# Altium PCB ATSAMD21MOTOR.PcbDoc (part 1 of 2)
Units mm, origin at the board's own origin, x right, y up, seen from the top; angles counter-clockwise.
Board outline 45.2 x 50.2 mm, 4 copper layers (Top Layer, GND, POWER, Bottom Layer), stack 0.8 mm thick; 92 components, 102 nets, 421 pads, 273 vias.
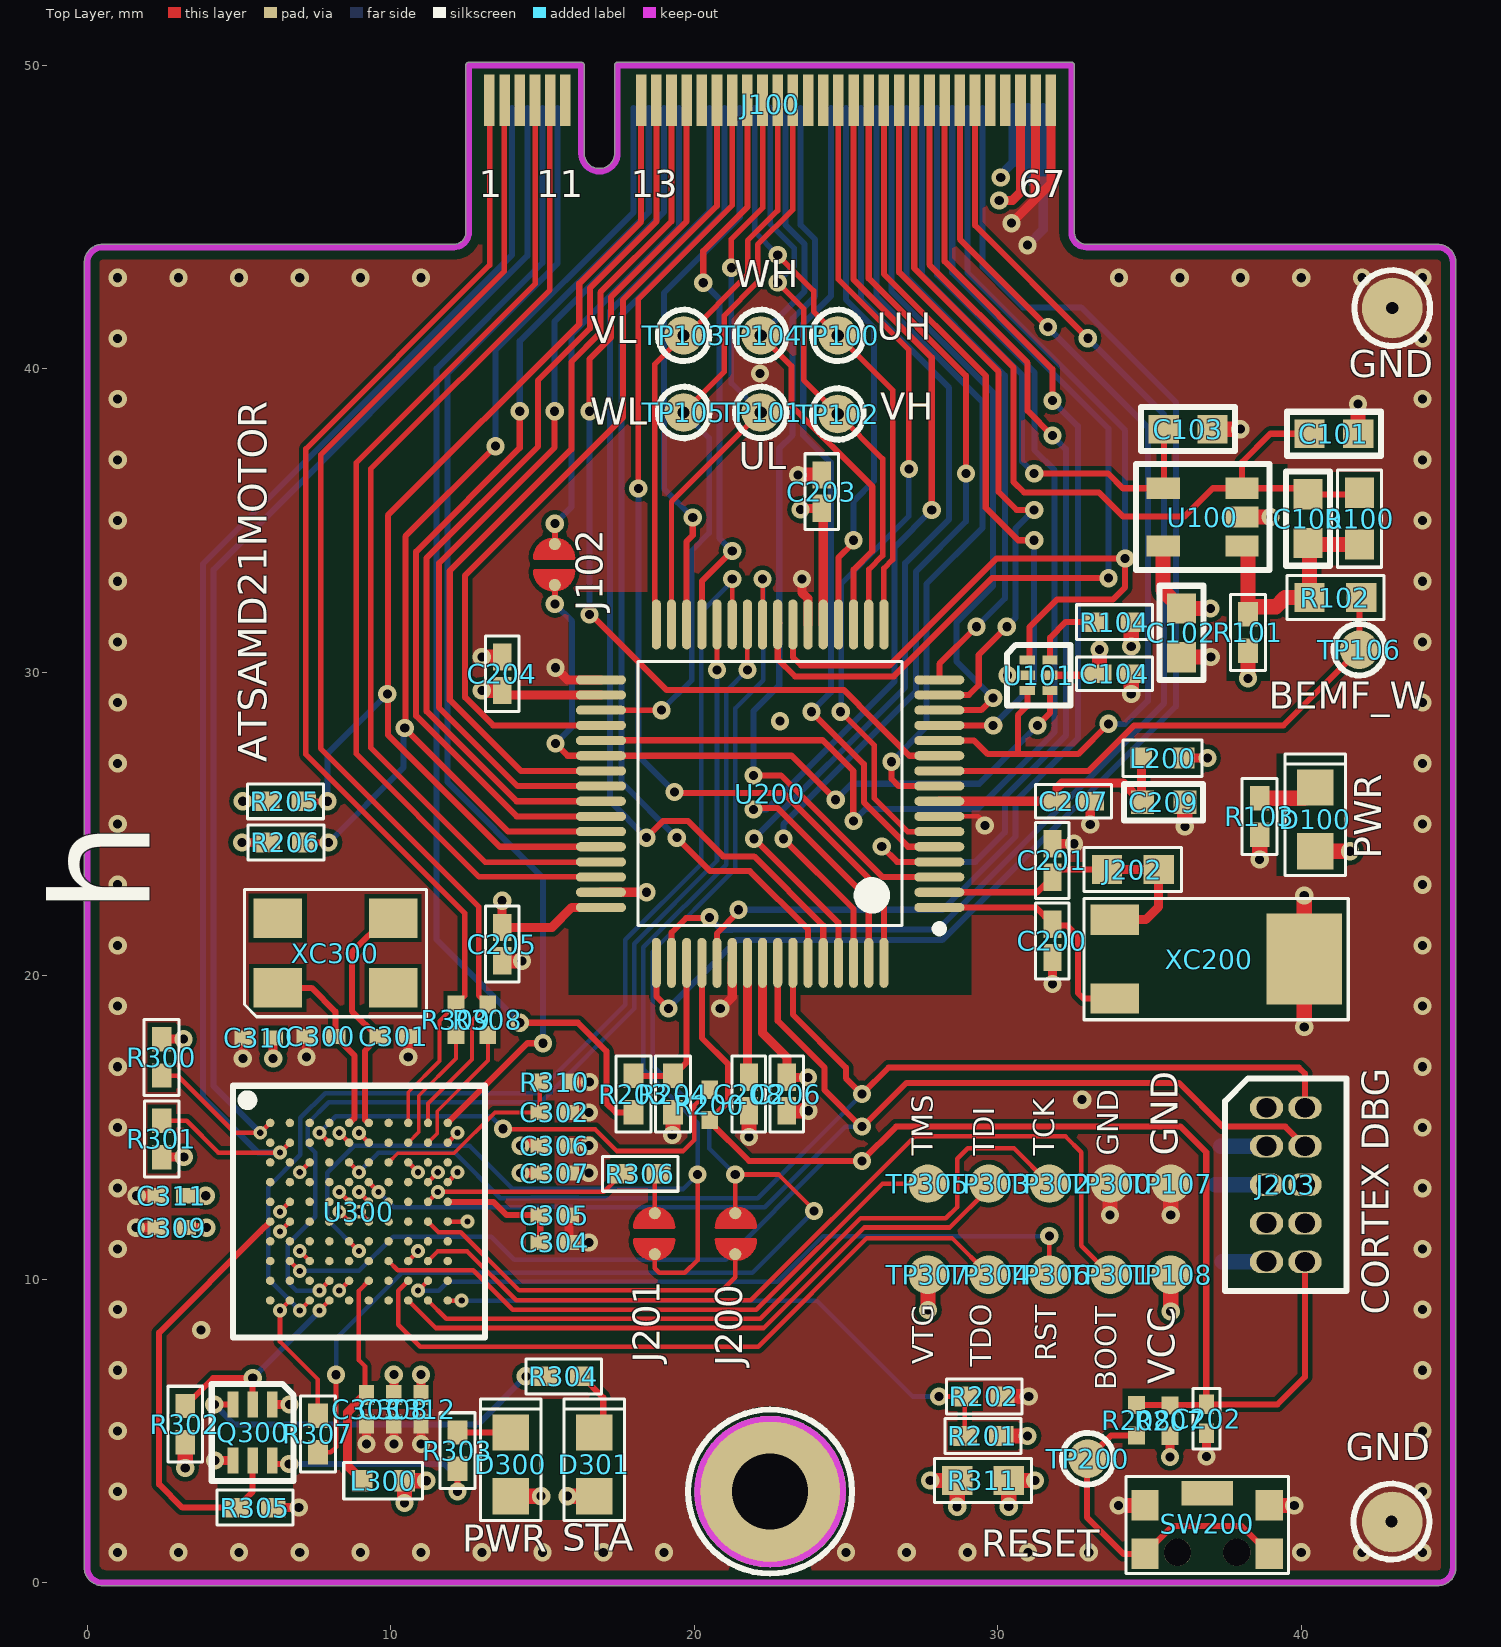
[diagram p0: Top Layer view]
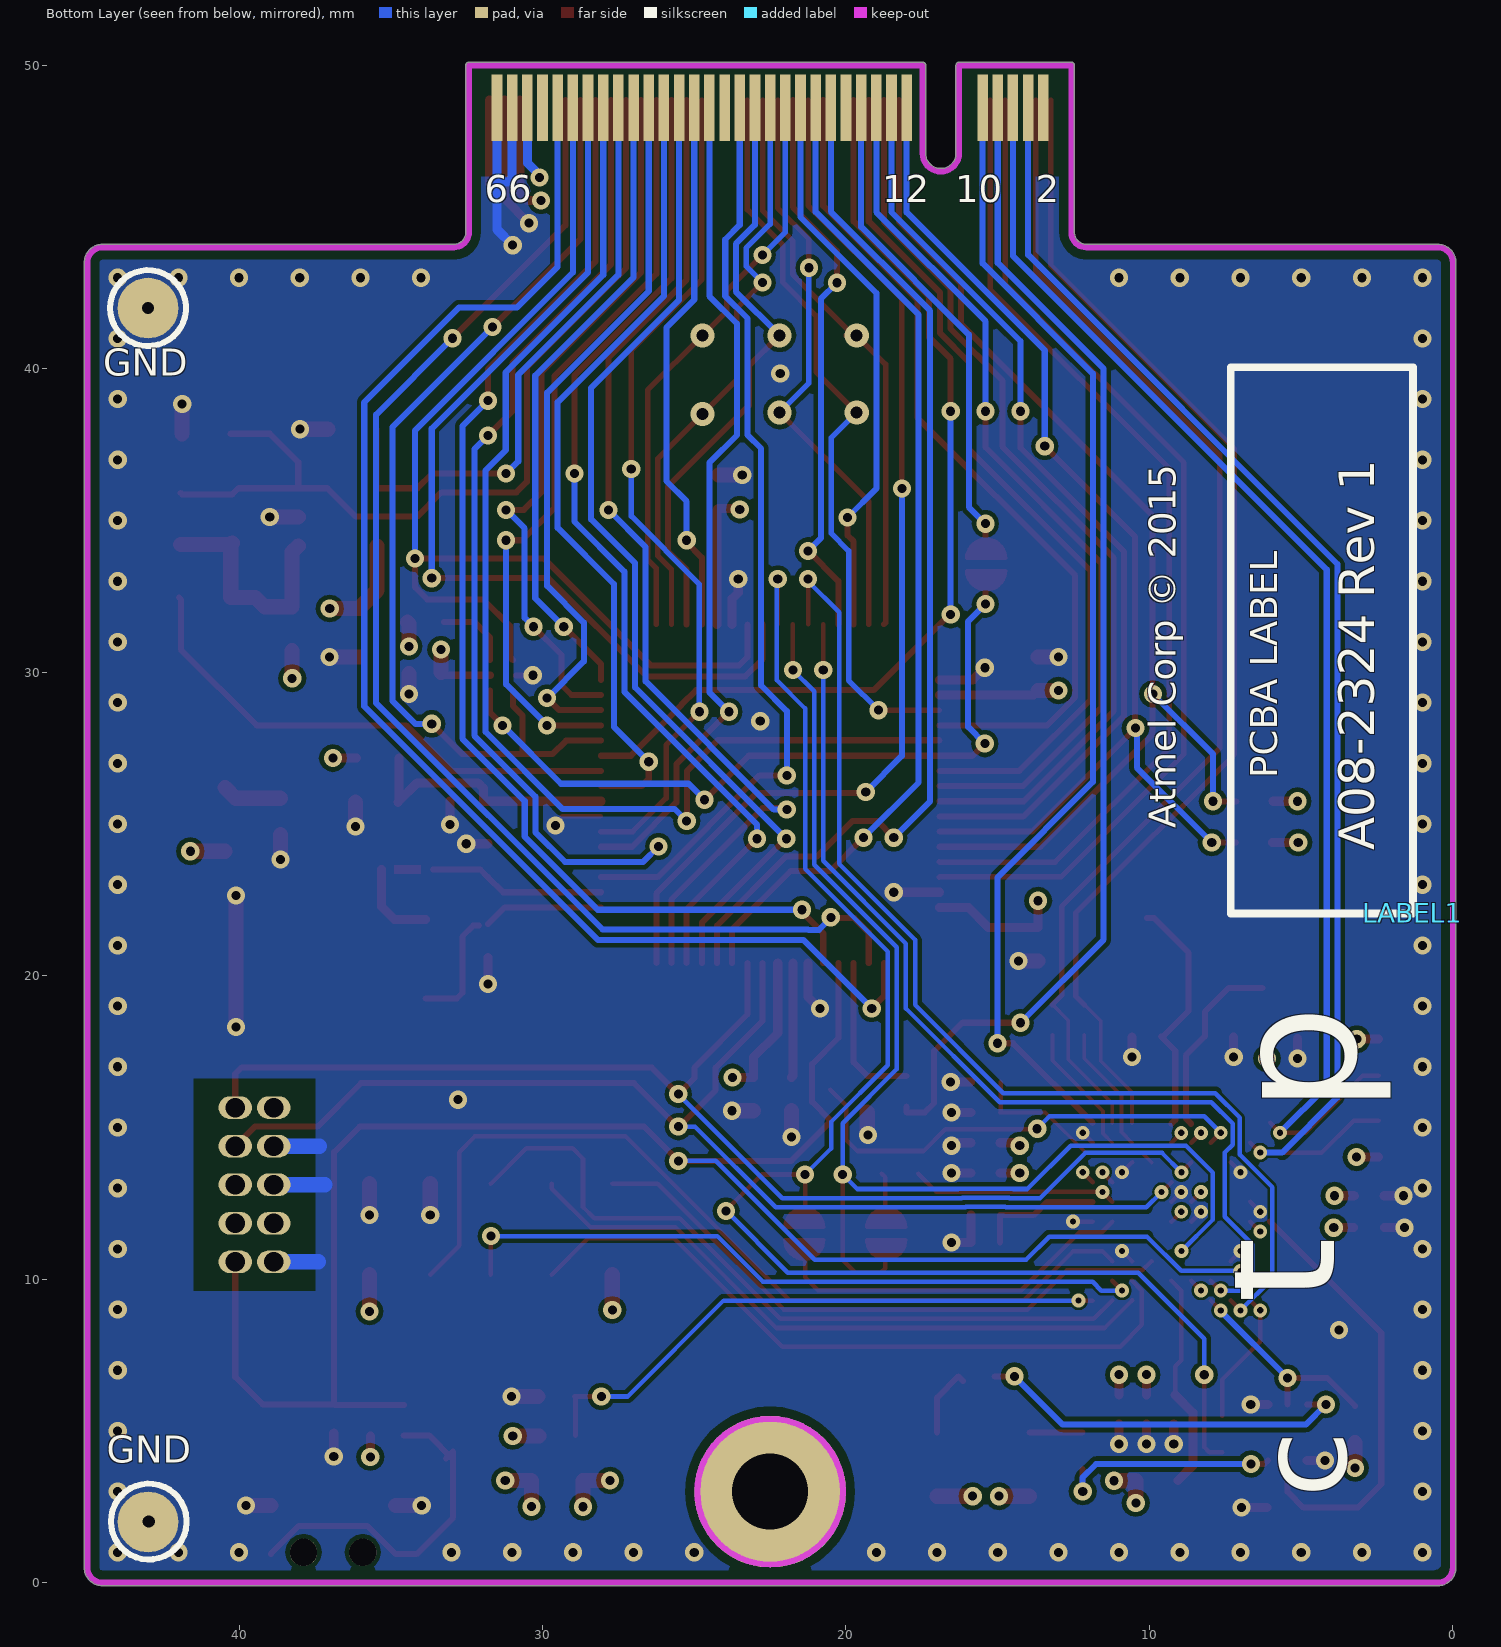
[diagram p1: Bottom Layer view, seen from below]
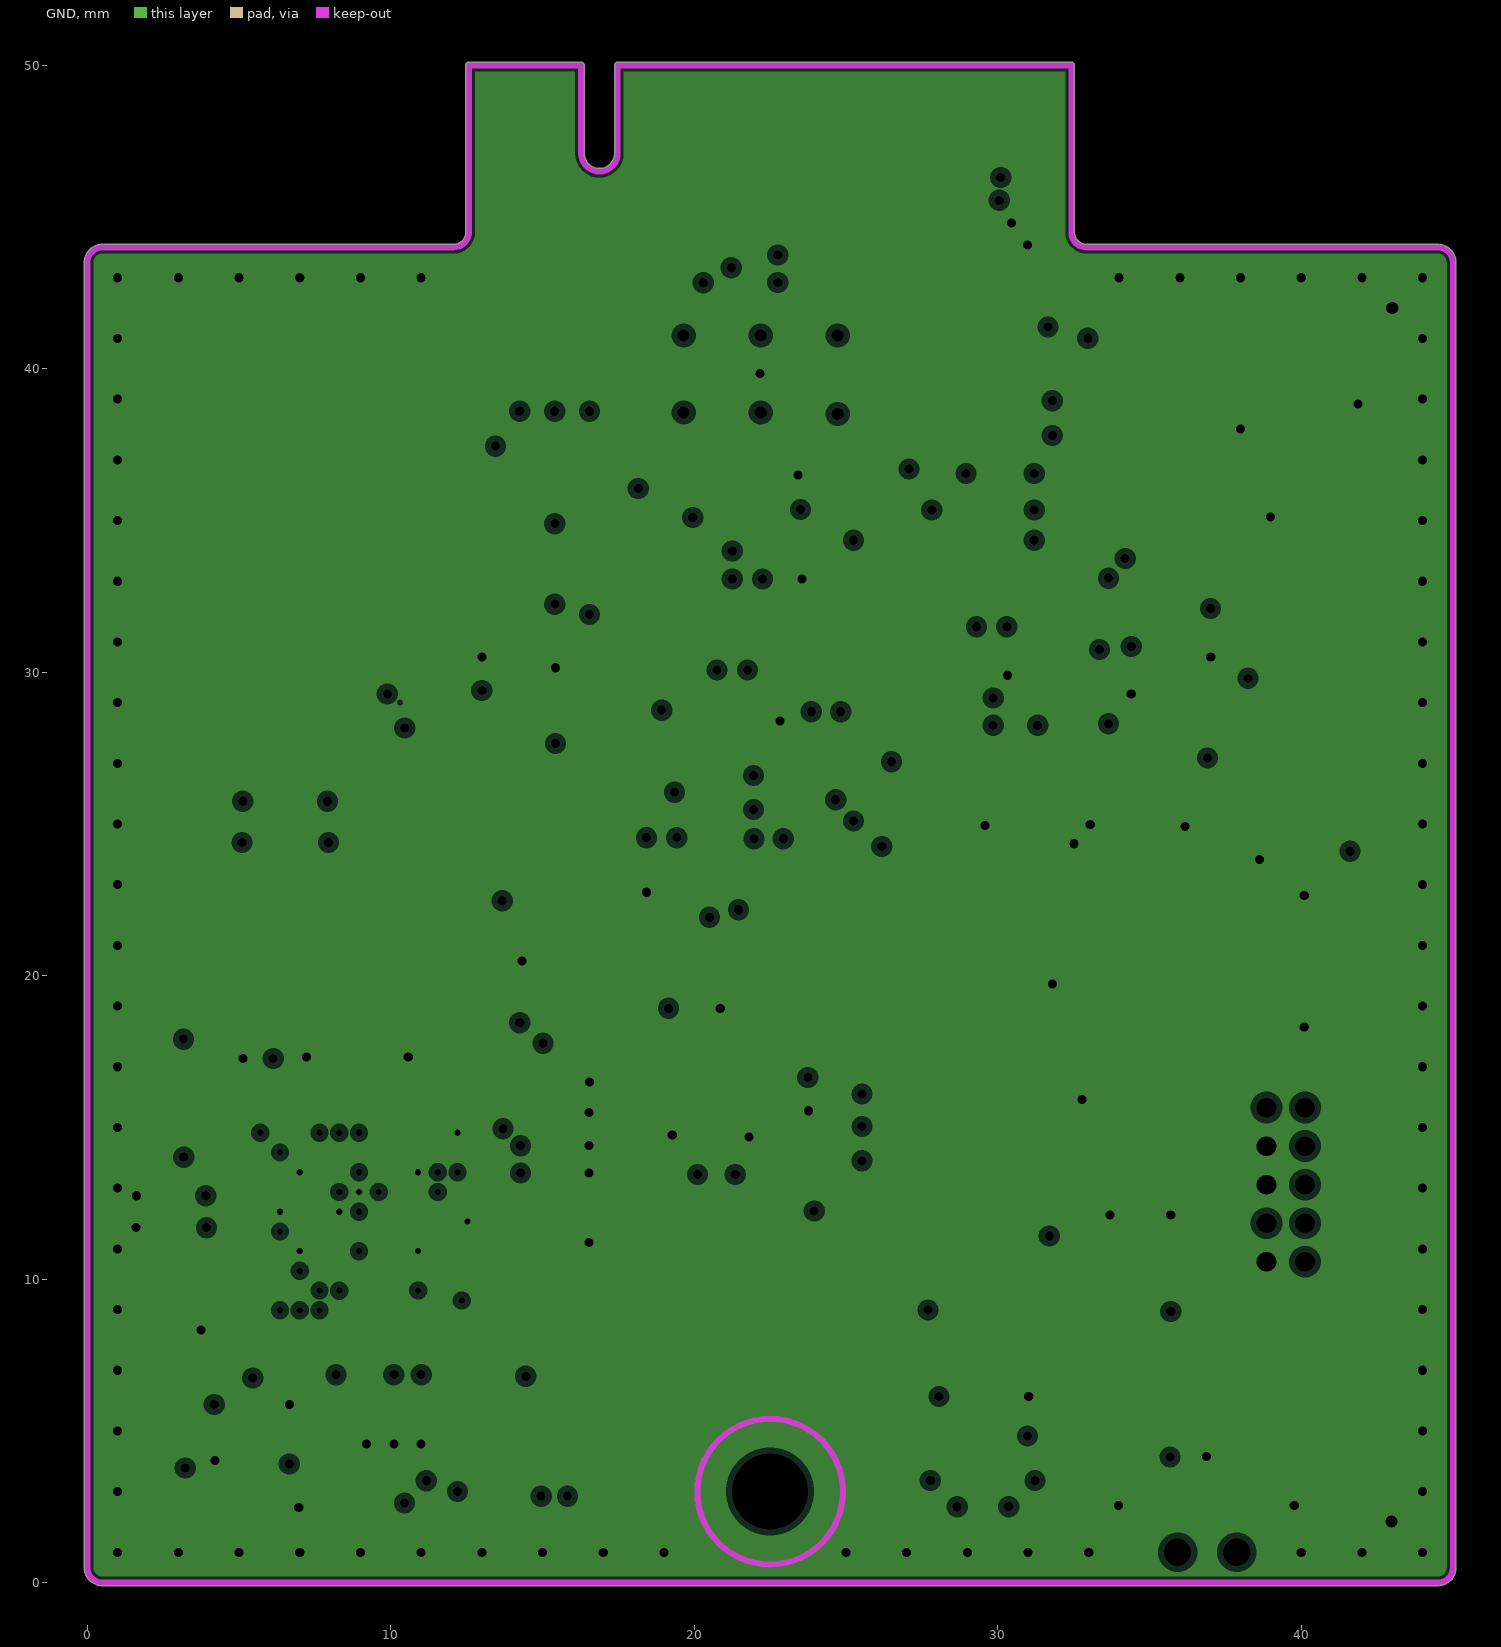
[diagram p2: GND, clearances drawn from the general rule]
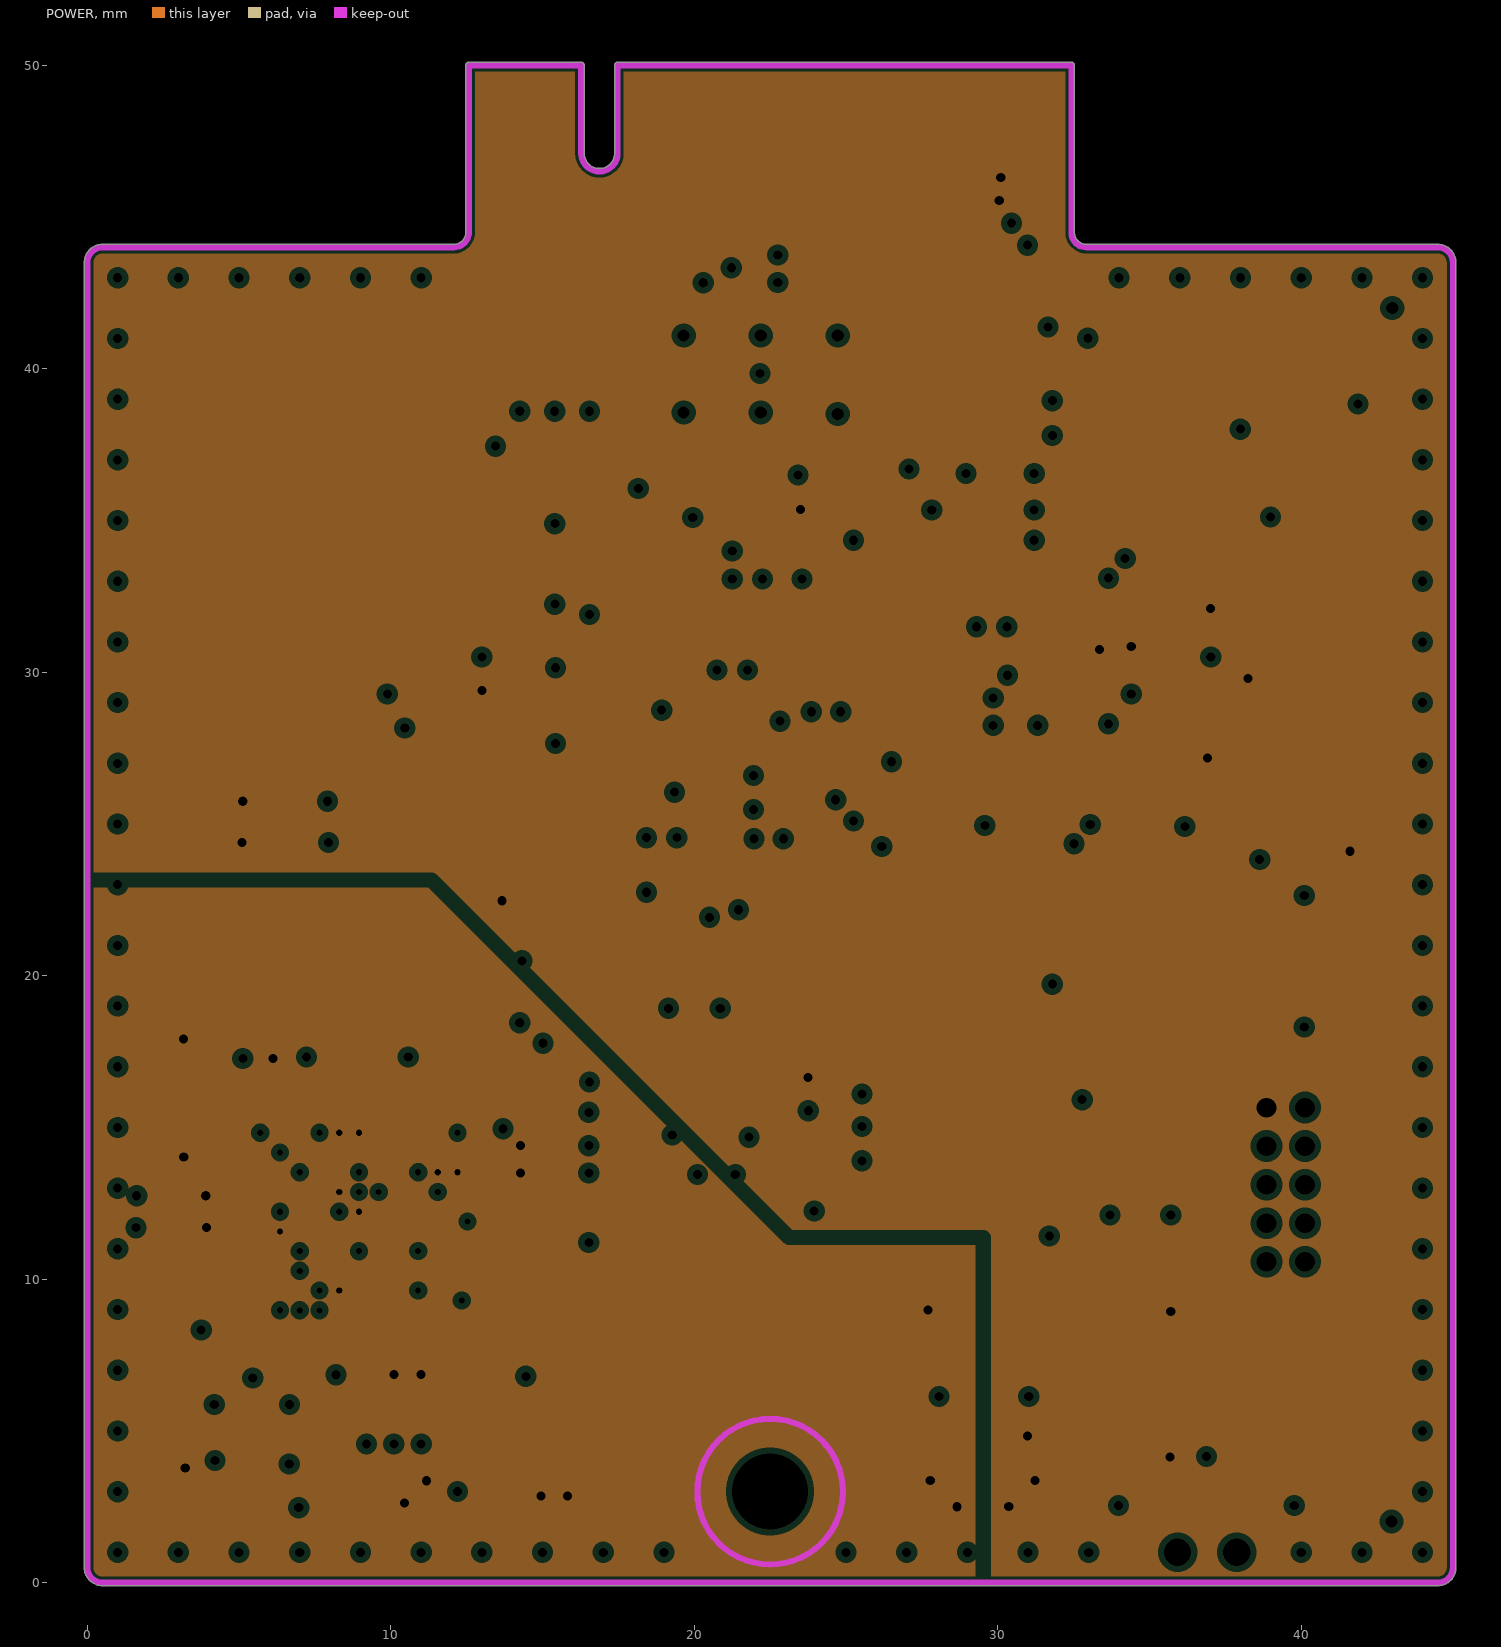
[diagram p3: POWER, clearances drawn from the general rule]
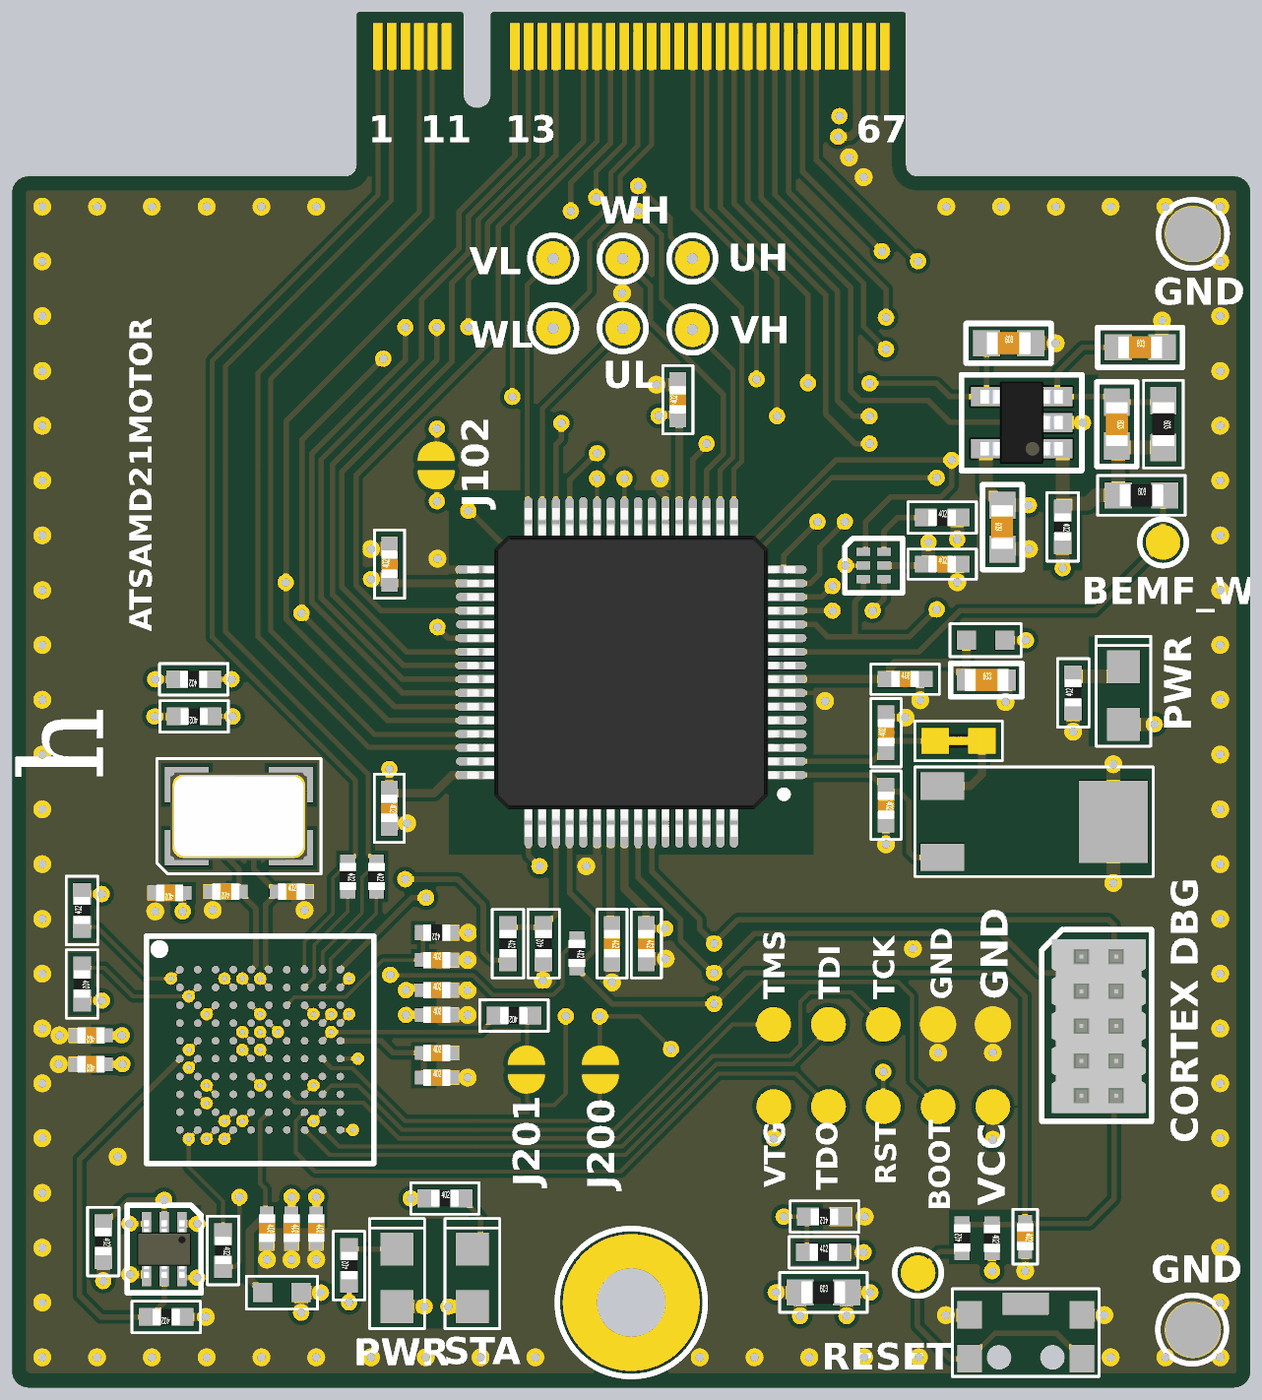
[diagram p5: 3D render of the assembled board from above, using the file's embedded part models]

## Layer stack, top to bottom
Top Solder: solder mask 0.0102, Solder Resist, Dk 3.5
Top Layer: signal copper 0.045
Dielectric1: prepreg 0.125, FR-4, Dk 4.2
GND: plane copper 0.035
Dielectric 4: core 0.4, Dk 4.2
POWER: plane copper 0.035
Dielectric3: prepreg 0.125, FR-4, Dk 4.2
Bottom Layer: signal copper 0.035
Bottom Solder: solder mask 0.0102, Solder Resist, Dk 3.5

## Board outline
0.497,-0.1 ccw(c0.5,0.5) 0.5,-0.1 44.5,-0.1 ccw(c44.5,0.5) 45.1,0.5 45.1,43.5 ccw(c44.5,43.5) 44.5,44.1 32.925,44.1 cw(c32.925,44.5) 32.525,44.5 32.525,50 ccw(c32.425,50) 32.425,50.1 17.475,50.1 ccw(c17.475,50) 17.375,50 17.375,47.1 cw(c16.875,47.1) 16.875,46.6 cw(c16.875,47.1) 16.375,47.1 16.375,50 ccw(c16.275,50) 16.275,50.1 12.575,50.1 ccw(c12.575,50) 12.475,50 12.475,44.5 cw(c12.075,44.5) 12.075,44.1 0.5,44.1 ccw(c0.5,43.5) -0.1,43.5 -0.1,0.5 ccw(c0.5,0.5)

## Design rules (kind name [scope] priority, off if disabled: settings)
AssemblyTestPointUsage "Schematic Assembly Testpoint Usage_6" [InNet('XOUT0')] p1: valid=1
AssemblyTestPointUsage "Schematic Assembly Testpoint Usage_5" [InNet('XIN0')] p2: valid=1
AssemblyTestPointUsage "Schematic Assembly Testpoint Usage_4" [InNet('EDBG_USB_HS_P')] p3: valid=1
AssemblyTestPointUsage "Schematic Assembly Testpoint Usage_3" [InNet('EDBG_USB_HS_N')] p4: valid=1
AssemblyTestPointUsage "Schematic Assembly Testpoint Usage_2" [InNet('EDBG_USB_FS_P')] p5: valid=1
AssemblyTestPointUsage "Schematic Assembly Testpoint Usage_1" [InNet('EDBG_USB_FS_N')] p6: valid=1
AssemblyTestPointUsage "Schematic Assembly Testpoint Usage_10" [InNet('PA00_XIN32')] p7: valid=1
AssemblyTestPointUsage "Schematic Assembly Testpoint Usage_9" [InNet('MCU_USB_P')] p8: valid=1
AssemblyTestPointUsage "Schematic Assembly Testpoint Usage_8" [InNet('PA01_XOUT32')] p9: valid=1
AssemblyTestPointUsage "Schematic Assembly Testpoint Usage_7" [InNet('NetJ202_1')] p10: valid=1
AssemblyTestPointUsage "Schematic Assembly Testpoint Usage" [InNet('MCU_USB_N')] p11: valid=1
AssemblyTestPointUsage [All] p12 off:
Clearance Clearance_1 [(OnLayer('Keep-Out Layer')) vs InPolygon] p1: gap=0.3
Clearance Clearance_EDBG [WithinRoom('EDBG')] p2: gap=0.089
Clearance [All] p3: gap=0.15
DiffPairsRouting [All] p1: maxlimit=0.3 minlimit=0.3 mostfreqgap=0.3 toplayer_minwidth=0.1 toplayer_maxwidth=0.18 toplayer_prefwidth=0.18 bottomlayer_minwidth=0.1 bottomlayer_maxwidth=0.18 bottomlayer_prefwidth=0.18 maxuncoupledlength=12.7
FabricationTestPointUsage [All] p1 off: valid=0 allowmultiple=FALSE
FabricationTestpoint [All] p1 off: side=3 testpointundercomponent=TRUE minsize=1.016 maxsize=2.54 preferedsize=1.524 minholesize=0 maxholesize=1.016 preferedholesize=0.813 testpointgrid=0.025 allowsidetop=TRUE allowsidebottom=TRUE usegrid=TRUE gridtolerance=0
HoleSize [All] p1: absolutevalues=TRUE maxlimit=4 minlimit=0.025 maxpercent=80.000 minpercent=20.000
MinimumSolderMaskSliver [All] p1: minsoldermaskwidth=0.1
PlaneClearance [All] p1: clearance=0.2
PlaneConnect PlaneConnect_pad [(InPadClass('All Pads'))] p1: planeconnectstyle=Relief reliefexpansion=0.508 reliefentries=4 reliefconductorwidth=0.254 reliefairgap=0.254
PlaneConnect [All] p2: planeconnectstyle=Direct reliefexpansion=0.508 reliefentries=4 reliefconductorwidth=0.254 reliefairgap=0.254
PolygonConnect PolygonConnect_freepad [isFree-1] p1: connectstyle=Direct reliefconductorwidth=0.254 reliefentries=4 polygonreliefangle="90 Angle" airgapwidth=0.254
PolygonConnect PolygonConnect_TH [All vs (InPadClass('All Pads'))] p2: connectstyle=Relief reliefconductorwidth=0.254 reliefentries=4 polygonreliefangle="90 Angle" airgapwidth=0.254
PolygonConnect PolygonConnect_ [All] p3: connectstyle=Direct reliefconductorwidth=0.254 reliefentries=4 polygonreliefangle="90 Angle" airgapwidth=0.254
RoomDefinition EDBG [All] p1: confinementstyle=ConfineOut formatcopy=TRUE lockcomponents=FALSE outline 4.801,8.074 4.801,16.374 13.101,16.374 13.101,8.074
RoutingVias [All] p1: holewidth=0.2 width=0.4 viastyle="Through Hole" minholewidth=0.2 minwidth=0.4 maxholewidth=0.4 maxwidth=0.8
SilkToSilkClearance [All] p1: silktosilkclearance=0.14
SilkToSolderMaskClearance SilkscreenOverComponentPads [IsPad] p1: minsilkscreentomaskgap=0.091 clearancetoexposedcopper=TRUE
SolderMaskExpansion SolderMaskExpansion_Tenting [IsVia AND NOT (IsFabTestpoint OR IsAssyTestpoint)] p1: expansion=-2
SolderMaskExpansion [All] p2: expansion=0.025
Width [All] p1: maxlimit=0.5 minlimit=0.1 preferedwidth=0.2 minimp=50.000000 maximp=50.000000 favimp=50.000000
20 further rules are at their usual default settings.

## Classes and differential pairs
component class "ATSAMD21MOTOR_TOP LEVEL": DOC1 FIXTURE1 FW1 LABEL1 PCB1 TEST1 TESTDOC1
component class Connector: C100 C101 C102 C103 C104 D100 J100 J102 R100 R101 R102 R103 R104 TP100 TP101 TP102 TP103 TP104 TP105 TP106 TP107 TP108 U100 U101
component class EDBG: C300 C301 C302 C303 C304 C305 C306 C307 C308 C309 C310 C311 C312 D300 D301 L300 Q300 R300 R301 R302 R303 R304 R305 R306 R307 R308 R309 R310 R311 TP300 TP301 TP302 TP303 TP304 TP305 TP306 TP307 U300 XC300
component class Target: C200 C201 C202 C203 C204 C205 C206 C207 C208 C209 J200 J201 J202 J203 L200 R200 R201 R202 R203 R204 R205 R206 R207 R208 SW200 TP200 U200 XC200
differential pair MCU_USB: +MCU_USB_P -MCU_USB_N
differential pair EDBG_USB_HS: +EDBG_USB_HS_P -EDBG_USB_HS_N
differential pair EDBG_USB_FS: +EDBG_USB_FS_P -EDBG_USB_FS_N

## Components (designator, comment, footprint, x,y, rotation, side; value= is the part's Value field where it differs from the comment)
C100 "#Farnell reference  722110RL" AP1-00002 40.225,35.06 r270 top
C101 "MPN back-ported from Escatec 29-09-2009" AP1-00002 41.075,37.86 r0 top
C102 "CAP-NONPOL" AP1-00002 36.05,31.3 r90 top
C103 "MPN back-ported from Escatec 29-09-2009" AP1-00002 36.275,38.01 r0 top
C104 "CAP-NONPOL" AP1-00001 33.85,29.95 r0 top
C200 "CAP-NONPOL" AP1-00001 31.8,21.15 r270 top
C201 "CAP-NONPOL" AP1-00001 31.8,23.8 r90 top
C202 "100n" AP1-00053 36.881,5.401 r270 top
C203 "CAP-NONPOL" AP1-00001 24.2,35.95 r90 top
C204 "CAP-NONPOL" AP1-00001 13.676,29.95 r90 top
C205 "CAP-NONPOL" AP1-00001 13.67,21.04 r270 top
C206 "CAP-NONPOL" AP1-00001 23.05,16.1 r270 top
C207 "CAP-NONPOL" AP1-00001 32.5,25.75 r0 top
C208 "CAP-NONPOL" AP1-00001 21.8,16.1 r270 top
C209 "CAP-NONPOL" AP1-00039 35.466,25.718 r0 top
C300 "22p" AP1-00053 7.7,18 r180 top
C301 "22p" AP1-00053 10.1,18 r0 top
C302 "10p" AP1-00053 15.401,15.498 r0 top
C303 "100n" AP1-00053 9.2,5.71 r270 top
C304 "Farnell no: 1288200" AP1-00053 15.401,11.211 r0 top
C305 "1 nF C0G" AP1-00053 15.401,12.11 r0 top
C306 "Farnell no: 1288200" AP1-00053 15.4,14.4 r0 top
C307 "100n" AP1-00053 15.401,13.498 r0 top
C308 "100n" AP1-00053 10.1,5.71 r270 top
C309 "100n" AP1-00053 2.776,11.699 r180 top
C310 "100n" AP1-00053 5.65,17.95 r180 top
C311 "Farnell no: 1288200" AP1-00053 2.776,12.749 r180 top
C312 "Farnell no: 1288200" AP1-00053 11,5.71 r270 top
D100 "LED_12" AP4-00013 40.465,25.153 r270 top
D300 "Green" AP4-00013 13.95,3.9 r270 top
D301 "Yellow" AP4-00013 16.7,3.9 r270 top
J100 "HEADER_67" AP9-00138 13.25,48.85 r180 top
J102 "SMD-STRAP_OPEN" AP9-00034 15.406,33.55 r90 top net-tie
J200 "SMD-STRAP_OPEN" AP9-00034 21.35,11.5 r270 top net-tie
J201 "SMD-STRAP_OPEN" AP9-00034 18.7,11.5 r90 top net-tie
J202 "" AP9-00044 34.45,23.5 r180 top net-tie
J203 "HEADER 2x5" AP8-00257 39.491,13.114 r270 top
L200 "BLM18PG471SN1" AP3-00005 35.432,27.171 r180 top
L300 "BLM18PG471SN1" AP3-00005 9.75,3.36 r180 top
LABEL1 "PCBA_LABEL" AP8-00317 1.32,22.053 r90 bottom
Q300 "Same as 2N7002 but with two MOSFETs in one package" AP5-00001 5.45,4.95 r270 top
R100 "R2" AP2-00001 41.925,35.06 r270 top
R101 "R2" AP2-00000 38.25,31.31 r270 top
R102 "R2" AP2-00001 41.125,32.46 r0 top
R103 "R2" AP2-00000 38.631,25.25 r90 top
R104 "R2" AP2-00000 33.85,31.65 r0 top
R200 "R2" AP2-00011 20.514,15.743 r270 top
R201 "R2" AP2-00000 29.513,4.835 r0 top
R202 "R2" AP2-00000 29.554,6.136 r180 top
R203 "R2" AP2-00000 18,16.1 r270 top
R204 "R2" AP2-00000 19.3,16.1 r90 top
R205 "R2" AP2-00000 6.529,25.748 r180 top
R206 "R2" AP2-00000 6.543,24.391 r180 top
R207 "R2" AP2-00011 35.675,5.339 r270 top
R208 "R2" AP2-00011 34.573,5.352 r90 top
R300 "R2" AP2-00000 2.45,17.31 r90 top
R301 "R2" AP2-00000 2.452,14.622 r270 top
R302 "R2" AP2-00000 3.226,5.223 r270 top
R303 "R2" AP2-00000 12.2,4.35 r90 top
R304 "R2" AP2-00000 15.7,6.8 r0 top
R305 "R2" AP2-00000 5.526,2.473 r180 top
R306 "R2" AP2-00000 18.219,13.474 r180 top
R307 "R2" AP2-00000 7.6,4.9 r270 top
R308 "R2" AP2-00011 13.2,18.55 r270 top
R309 "R2" AP2-00011 12.15,18.55 r270 top
R310 "R2" AP2-00011 15.401,16.498 r180 top
R311 "R2" AP2-00001 29.513,3.368 r0 top
SW200 "Reset switch on PCB Edge" AP8-00648 36.9,1.95 r0 top
TP100 "TESTPOINT" AP8-00010#1 24.73,41.1 r90 top
TP101 "TESTPOINT" AP8-00010#1 22.19,38.56 r90 top
TP102 "TESTPOINT" AP8-00010#2 24.73,38.56 r90 top
TP103 "TESTPOINT" AP8-00010#1 19.65,41.1 r90 top
TP104 "TESTPOINT" AP8-00010#1 22.19,41.1 r90 top
TP105 "TESTPOINT" AP8-00010#1 19.65,38.56 r90 top
TP106 "TESTPOINT" AP8-00010#1 41.914,30.745 r270 top
TP107 "TESTPOINT" AP8-00010#3 36.257,12.968 r90 top
TP108 "TESTPOINT" AP8-00010#4 35.647,10.182 r90 top
TP200 "TESTPOINT" AP8-00010#1 32.97,4.085 r90 top
TP300 "TESTPAD" AP8-00010#1 33.7,13.15 r0 top
TP301 "TESTPAD" AP8-00010#1 33.7,10.15 r0 top
TP302 "TESTPAD" AP8-00010#1 31.7,13.15 r0 top
TP303 "TESTPAD" AP8-00010#1 29.7,13.15 r0 top
TP304 "TESTPAD" AP8-00010#1 29.7,10.15 r0 top
TP305 "TESTPAD" AP8-00010#1 27.7,13.15 r0 top
TP306 "TESTPAD" AP8-00010#1 31.7,10.15 r0 top
TP307 "TESTPAD" AP8-00010#1 27.7,10.15 r0 top
U100 "TS3021IYLT" AP6-00014 36.75,35.115 r180 top
U101 "7S175" AP6-00076 31.35,29.9 r0 top
U200 "TQFP64" AP6-00173 22.5,26 r180 top
U300 "100 ball VFBGA" AP6-00206 8.951,12.224 r0 top
XC200 "Farnell order no:1539364" AP7-00044 33.85,20.55 r270 top
XC300 "12.0MHz" AP7-00039 8.176,20.749 r0 top

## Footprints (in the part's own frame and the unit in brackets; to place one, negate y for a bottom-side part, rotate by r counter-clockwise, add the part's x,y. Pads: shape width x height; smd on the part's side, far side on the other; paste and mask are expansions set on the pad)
AP1-00001 [mm] "Standard 0402 SMD capacitor footprint"
  rect 0.9x0.6 smd: 1(-0.55,0) 2(0.55,0)
  silkscreen extent -1.25,-0.55 1.25,0.55, body extent -0.5,-0.3 0.5,0.3, height 0.2
AP1-00002 [mm]
  rect 1x0.95 smd: 1(-0.8,0) 2(0.8,0)
  silkscreen extent -1.55,-0.72 1.55,0.72, body extent -0.8,-0.4 0.8,0.4, height 0.3
AP1-00039 [mil] "Capacitor 0603 Hight 0.8mm"
  rect 30x30 smd: 1(-27.5,0) 2(27.5,0)
  silkscreen extent -52,-24 51,24, body extent -31,-16 32,16, height 12
AP1-00053 [mm] "Chip Capacitor, 2-Leads, Body 1.0x0.5mm, IPC High Density"
  rect 0.65x0.5 smd: 1(-0.475,0) 2(0.475,0)
  silkscreen extent -1,-0.45 1,0.45, body extent -0.5,-0.3 0.5,0.3, height 0.2
AP2-00000 [mm] "Standard 0402 SMD resistor footprint"
  rect 0.8x0.65 smd: 1(-0.6,0) 2(0.6,0)
  silkscreen extent -1.25,-0.58 1.25,0.58, body extent -0.5,-0.3 0.5,0.3, height 0.2
AP2-00001 [mm]
  rect 1x0.95 smd: 1(-0.85,0) 2(0.85,0)
  silkscreen extent -1.6,-0.72 1.6,0.72, body extent -0.8,-0.4 0.8,0.4, height 0.3
AP2-00011 [mm] "Chip Resistor, 2-Leads, Body 1,0x0,5mm, IPC High Density"
  rect 0.6x0.55 smd: 1(-0.5,0) 2(0.5,0)
  body extent -0.5,-0.3 0.5,0.3, height 0.2
AP3-00005 [mm]
  rect 0.7x0.7 smd: 1(-0.7,0) 2(0.7,0)
  silkscreen extent -1.3,-0.6 1.3,0.6, body extent -0.83,-0.41 0.82,0.41, height 0.8
AP4-00013 [mm] "0805 diode footprint"
  rect 1.2x1.2 smd: 1(-1.05,0) 2(1.05,0)
  silkscreen extent -2.16,-1 1.85,1, body extent -1,-0.63 1,0.63, height 1.1
AP5-00001 [mm]
  rect 0.85x0.35 smd: 1(-0.925,0.65) 2(-0.925,0) 3(-0.925,-0.65) 4(0.925,-0.65) 5(0.925,0) 6(0.925,0.65)
  silkscreen extent -1.6,-1.35 1.6,1.35, body extent -1.05,-1 1.05,1, height 0.95
AP6-00014 [mm]
  rect 1.1x0.7 smd mask+0.07: 1(-1.3,0.95) 2(-1.3,0) 3(-1.3,-0.95) 4(1.3,-0.95) 5(1.3,0.95)
  silkscreen extent -2.2,-1.75 2.2,1.75, body extent -1.5,-1.5 1.5,1.5, height 1.3
AP6-00076 [mm]
  rect 0.5x0.3 smd: 1(-0.375,0.5) 2(-0.375,0) 3(-0.375,-0.5) 4(0.375,-0.5) 5(0.375,0) 6(0.375,0.5)
  silkscreen extent -1.05,-1 1.05,1, body extent -0.53,-0.75 0.53,0.75, height 0.55
AP6-00173 [mm] "TSQFP, 64-Leads, Body 12.0x12.0mm (max), Pitch 0.50mm, IPC Medium Density"
  oval 1.65x0.3 smd: 1(-5.575,3.75) 2(-5.575,3.25) 3(-5.575,2.75) 4(-5.575,2.25) 5(-5.575,1.75) 6(-5.575,1.25) 7(-5.575,0.75) 8(-5.575,0.25) 9(-5.575,-0.25) 10(-5.575,-0.75) 11(-5.575,-1.25) 12(-5.575,-1.75) 13(-5.575,-2.25) 14(-5.575,-2.75) 15(-5.575,-3.25) 16(-5.575,-3.75) 33(5.575,-3.75) 34(5.575,-3.25) 35(5.575,-2.75) 36(5.575,-2.25) 37(5.575,-1.75) 38(5.575,-1.25) 39(5.575,-0.75) 40(5.575,-0.25) 41(5.575,0.25) 42(5.575,0.75) 43(5.575,1.25) 44(5.575,1.75) 45(5.575,2.25) 46(5.575,2.75) 47(5.575,3.25) 48(5.575,3.75)
  oval 0.3x1.65 smd: 17(-3.75,-5.575) 18(-3.25,-5.575) 19(-2.75,-5.575) 20(-2.25,-5.575) 21(-1.75,-5.575) 22(-1.25,-5.575) 23(-0.75,-5.575) 24(-0.25,-5.575) 25(0.25,-5.575) 26(0.75,-5.575) 27(1.25,-5.575) 28(1.75,-5.575) 29(2.25,-5.575) 30(2.75,-5.575) 31(3.25,-5.575) 32(3.75,-5.575) 49(3.75,5.575) 50(3.25,5.575) 51(2.75,5.575) 52(2.25,5.575) 53(1.75,5.575) 54(1.25,5.575) 55(0.75,5.575) 56(0.25,5.575) 57(-0.25,5.575) 58(-0.75,5.575) 59(-1.25,5.575) 60(-1.75,5.575) 61(-2.25,5.575) 62(-2.75,5.575) 63(-3.25,5.575) 64(-3.75,5.575)
  silkscreen extent -5.7,-4.35 4.35,4.57, body extent -6,-6 6,6, height 1.2
AP6-00206 [mm] "100 ball (10x10 array) VFBGA. Pitch 0.65 mm. Width: 7 mm. Length: 7mm. Height: 1 mm"
  round 0.28 smd: A1(-2.925,2.925) A2(-2.275,2.925) A3(-1.625,2.925) A4(-0.975,2.925) A5(-0.325,2.925) A6(0.325,2.925) A7(0.975,2.925) A8(1.625,2.925) A9(2.275,2.925) A10(2.925,2.925) B1(-2.925,2.275) B2(-2.275,2.275) B3(-1.625,2.275) B4(-0.975,2.275) B5(-0.325,2.275) B6(0.325,2.275) B7(0.975,2.275) B8(1.625,2.275) B9(2.275,2.275) B10(2.925,2.275) C1(-2.925,1.625) C2(-2.275,1.625) C3(-1.625,1.625) C4(-0.975,1.625) C5(-0.325,1.625) C6(0.325,1.625) C7(0.975,1.625) C8(1.625,1.625) C9(2.275,1.625) C10(2.925,1.625) D1(-2.925,0.975) D2(-2.275,0.975) D3(-1.625,0.975) D4(-0.975,0.975) D5(-0.325,0.975) D6(0.325,0.975) D7(0.975,0.975) D8(1.625,0.975) D9(2.275,0.975) D10(2.925,0.975) E1(-2.925,0.325) E2(-2.275,0.325) E3(-1.625,0.325) E4(-0.975,0.325) E5(-0.325,0.325) E6(0.325,0.325) E7(0.975,0.325) E8(1.625,0.325) E9(2.275,0.325) E10(2.925,0.325) F1(-2.925,-0.325) F2(-2.275,-0.325) F3(-1.625,-0.325) F4(-0.975,-0.325) F5(-0.325,-0.325) F6(0.325,-0.325) F7(0.975,-0.325) F8(1.625,-0.325) F9(2.275,-0.325) F10(2.925,-0.325) G1(-2.925,-0.975) G2(-2.275,-0.975) G3(-1.625,-0.975) G4(-0.975,-0.975) G5(-0.325,-0.975) G6(0.325,-0.975) G7(0.975,-0.975) G8(1.625,-0.975) G9(2.275,-0.975) G10(2.925,-0.975) H1(-2.925,-1.625) H2(-2.275,-1.625) H3(-1.625,-1.625) H4(-0.975,-1.625) H5(-0.325,-1.625) H6(0.325,-1.625) H7(0.975,-1.625) H8(1.625,-1.625) H9(2.275,-1.625) H10(2.925,-1.625) J1(-2.925,-2.275) J2(-2.275,-2.275) J3(-1.625,-2.275) J4(-0.975,-2.275) J5(-0.325,-2.275) J6(0.325,-2.275) J7(0.975,-2.275) J8(1.625,-2.275) J9(2.275,-2.275) J10(2.925,-2.275) K1(-2.925,-2.925) K2(-2.275,-2.925) K3(-1.625,-2.925) K4(-0.975,-2.925) K5(-0.325,-2.925) K6(0.325,-2.925) K7(0.975,-2.925) K8(1.625,-2.925) K9(2.275,-2.925) K10(2.925,-2.925)
  silkscreen extent -4.15,-4.15 4.15,4.15, body extent -3.5,-3.5 3.5,3.5, height 1.01
AP7-00039 [mm] "FOX FQ5032B"
  rect 1.6x1.3 smd: 1(-1.9,-1.15) 2(1.9,-1.15) 3(1.9,1.15) 4(-1.9,1.15)
  silkscreen extent -3,-2.1 3,2.1, body extent -2.5,-1.6 2.5,1.6, height 1
AP7-00044 [mm]
  rect 1x1.6 smd: 1(-1.3,0) 2(1.3,0)
  rect 3x2.5 smd: 3(0,6.25)
  silkscreen extent -2,-1 2,7.7, body extent -1.5,-0.7 1.5,7.4, height 2.08
AP8-00010#1 [mm] "Testpad 50mil"
  round 1.27 smd paste-0.635: 1(0,0)
AP8-00010#2 [mm] "Testpad 50mil"
  round 1.27 smd paste-0.635: 1(-0.05,0)
AP8-00010#3 [mm] "Testpad 50mil"
  round 1.27 smd paste-0.635: 1(0.182,0.557)
AP8-00010#4 [mm] "Testpad 50mil"
  round 1.27 smd paste-0.635: 1(-0.032,-0.053)
AP8-00257 [mm]
  oval 0.75x1.1 hole 0.65: 1(-2.54,-0.635) 2(-2.54,0.635) 3(-1.27,-0.635) 4(-1.27,0.635) 5(0,-0.635) 6(0,0.635) 7(1.27,-0.635) 8(1.27,0.635) 9(2.54,-0.635) 10(2.54,0.635)
  silkscreen extent -3.5,-2 3.5,2, body extent -3.15,-1.64 3.2,1.79, height 3.88
AP8-00317 [mm] "Placement area for 18x6mm sticker"
  silkscreen extent 0,0 18,6
AP8-00648 [mm] "Microminiature SMT Side Actuated"
  rect 0.9x1 smd: 1(-2.05,-1) 2(-2.05,0.6) 4(2.05,0.6) 5(2.05,-1)
  rect 1.7x0.8 smd: 3(0,1)
  round 0.9 hole 0.9 unplated mask+0: 6(-0.975,-0.95) 7(0.975,-0.95)
  silkscreen extent -2.68,-1.65 2.68,1.55
AP9-00034 [mm] "PCB implemented strap, open"
  round 0.4 smd paste-0.4 mask-0.4: 1(-0.675,0) 2(0.675,0)
  Top Layer region: 0.2,0.675 0.482,0.611 0.708,0.43 0.834,0.17 0.834,-0.12 0.708,-0.38 0.482,-0.561 0.2,-0.625 0.2,-0.625
  Top Layer region: -0.2,-0.625 -0.482,-0.561 -0.708,-0.38 -0.834,-0.12 -0.834,0.17 -0.708,0.43 -0.482,0.611 -0.2,0.675 -0.2,0.675
  Top Layer lines w0.1: -0.2,0.675 ccw(c-0.2,0.025) -0.2,-0.625 -0.2,0.675 ; 0.2,0.675 cw(c0.2,0.025) 0.2,-0.625 0.2,0.675
AP9-00044 [mm]
  rect 1x0.95 smd paste-1: 1(-0.85,0) 2(0.85,0)
  Top Layer region: -0.45,-0.15 0.45,-0.15 0.45,0.15 -0.45,0.15
  silkscreen extent -1.6,-0.72 1.6,0.73, body extent -0.8,-0.4 0.8,0.4, height 0.3
AP9-00138 [mm]
  rect 0.35x1.7 smd paste-10: 1(0,0) 3(-0.5,0) 5(-1,0) 7(-1.5,0) 9(-2,0) 11(-2.5,0) 13(-5,0) 15(-5.5,0) 17(-6,0) 19(-6.5,0) 21(-7,0) 23(-7.5,0) 25(-8,0) 27(-8.5,0) 29(-9,0) 31(-9.5,0) 33(-10,0) 35(-10.5,0) 37(-11,0) 39(-11.5,0) 41(-12,0) 43(-12.5,0) 45(-13,0) 47(-13.5,0) 49(-14,0) 51(-14.5,0) 53(-15,0) 55(-15.5,0) 57(-16,0) 59(-16.5,0) 61(-17,0) 63(-17.5,0) 65(-18,0) 67(-18.5,0)
  rect 0.35x2.2 smd far side paste-10: 2(-0.25,0.25) 4(-0.75,0.25) 6(-1.25,0.25) 8(-1.75,0.25) 10(-2.25,0.25) 12(-4.75,0.25) 14(-5.25,0.25) 16(-5.75,0.25) 18(-6.25,0.25) 20(-6.75,0.25) 22(-7.25,0.25) 24(-7.75,0.25) 26(-8.25,0.25) 28(-8.75,0.25) 30(-9.25,0.25) 32(-9.75,0.25) 34(-10.25,0.25) 36(-10.75,0.25) 38(-11.25,0.25) 40(-11.75,0.25) 42(-12.25,0.25) 44(-12.75,0.25) 46(-13.25,0.25) 48(-13.75,0.25) 50(-14.25,0.25) 52(-14.75,0.25) 54(-15.25,0.25) 56(-15.75,0.25) 58(-16.25,0.25) 60(-16.75,0.25) 62(-17.25,0.25) 64(-17.75,0.25) 66(-18.25,0.25)

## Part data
C100: library part A01-0435, "Ceramic Cap, 100pF, 50V, +/-10%, 0603, X7R"
C101 C103: library part A01-0101, "Ceramic capacitor, SMD 0603, X7R, 50V, ±10 %"
C102: library part A01-0087, "Ceramic capacitor, SMD 0603, X7R, 16V, +/-10 %"
C104 C202 C203 C204 C205 C206 C207 C208 C303 C307 C308 C309 C310: library part A01-0246, "Ceramic capacitor, SMD 0402, X7R, 16V, +/-10%"
C200 C201: library part A01-0013, "Ceramic capacitor, SMD 0402, NP0, 50V, +/-5%"
C209: library part A01-0491, "Ceramic capacitor, SMD 0603, X5R, 16V, 10UF ± 20% (High Density)"
C300 C301: library part A01-0019, "Ceramic capacitor, SMD 0402, NP0, 50V, +/-5%"
C302: library part A01-0015, "Ceramic capacitor, SMD 0402, NP0, 50V, +/-5%"
C304 C306 C311 C312: library part A01-0300, "Ceramic capacitor, SMD 0402, X5R, 6.3V, +/-20%"
C305: library part A01-0321, "Ceramic capacitor, SMD 0402, C0G, 50V, +/-5%"
D100: library part A10-0017, "LED, Red, Wave length=639nm, SMD 0805, ±70°"
D300: library part A10-0018, "LED, Green, Wave length=575nm, SMD 0805, ±70°"
D301: library part A10-0019, "LED, Yellow, Wave length=591nm, SMD 0805, ±70°"
J100: library part A08-2293, "2199230-3 M.2 NGFF Module card layout"
J102 J200 J201: library part A09-0483, "Default open SMD strap"
J202: library part A09-0783, "Default closed SMD strap, 0603 size"
J203: library part A08-0385, "2x5 pin header, 1.27mm pitch, THM"
L200 L300: library part A03-0035, "SMD RF inductor 0603. Z=470Ohm (@100MHz), Max R(dc)=0.65Ohm, Max current=1A"
LABEL1: library part A09-0611, "PCBA identification label PP Top White Gloss"
Q300: library part A05-0051, "Dual N-Channel MOSFET, 60V, 115mA cont,RDS(ON) < 7.5 Ohm @50mA@5V, SOT-363"
R100: library part A02-0122, "Thick film resistor, SMD 0603, 1/10W, 1%"
R101 R104: library part A02-0236, "Thick film resistor, SMD 0402, 1/16W, 1%"
R102: library part A02-0062, "Thick film resistor, SMD 0603, 1/10W, 1%"
R103 R303 R304 R306 R307: library part A02-0200, "Thick film resistor, SMD 0402, 1/16W, 1%"
R200 R208 R308 R309: library part A02-0178, "Thick film resistor, SMD 0402, 1/16W, 1%"
R201 R202 R204: library part A02-0252, "Thick film resistor, SMD 0402, 1/16W, 1%"
R203: library part A02-0247, "Thick film resistor, SMD 0402, 1/16W, 1%"
R205 R206: library part A02-0228, "Thick film resistor, SMD 0402, 1/16W, 1%"
R207: library part A02-0260, "Thick film resistor, SMD 0402, 1/16W, 1%"
R300 R301: library part A02-0212, "Thick film resistor, SMD 0402, 1/16W, 1%"
R302 R305: library part A02-0284, "Thick film resistor, SMD 0402, 1/16W, 1%"
R310: library part A02-0539, "Thick film resistor, SMD 0402, 1/16W, 1%"
R311: library part A02-0001, "Thick film resistor, SMD 0603, 1/10W, 1%"
SW200: library part A08-1554, "KMS Series Microminiature SMT Side Actuated with pegs"
TP100 TP101 TP102 TP103 TP104 TP105 TP106 TP107 TP108 TP200 TP300 TP301 TP302 TP303 TP304 TP305 TP306 TP307: library part A08-0004, "Single SMD testpad"
U100: library part A06-1251, "Analog Comparators RR 1.8V Comparator 38ns 73uA 1.8 to 5V"
U101: library part A06-0015, "TinyLogic D-Type Flip-Flop with asynchronous Clear"
U200: library part A06-1041, "Atmel 32-bit RISC MCU 64pin"
U300: library part A06-0736, "AVR 32-bit RISC MCU"
XC200: library part A07-0052, "32k768 crystal, +-20ppm, CL=7pF, max ESR 60kOhm, SMD"
XC300: library part A07-0042, "Fox FQ5032B 12.0MHz SMD crystal 738B-12"

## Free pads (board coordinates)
  round 5 hole 2.5: 0(22.5,3)
  round 2 smd: 1(43,2) 1(43,42)
  round 2 smd far side: 1(43,2) 1(43,42)

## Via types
v1: diameter 0.6, hole 0.3, Top Layer to Bottom Layer, 234 vias
v2: diameter 0.457, hole 0.203, Top Layer to Bottom Layer, 30 vias
v3: diameter 0.8, hole 0.4, Top Layer to Bottom Layer, 8 vias
v4: diameter 0.457, hole 0.2, Top Layer to Bottom Layer, 1 vias

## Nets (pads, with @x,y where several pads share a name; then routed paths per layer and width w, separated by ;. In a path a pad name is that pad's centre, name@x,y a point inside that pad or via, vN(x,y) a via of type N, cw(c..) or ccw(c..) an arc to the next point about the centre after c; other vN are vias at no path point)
ATA_RESET: J100.35
ATA_SLEEP: J100.37
ATA_WD: J100.36
BEMF_COM_W: R102.2 TP106.1 U200.10 | length 17.2
  Top Layer w0.2: U200.10@28.075,26.75 32.997,26.75 34.495,28.247 39.417,28.247 TP106.1@41.914,30.745 41.914,32.4 R102.2@41.975,32.46
BEMF_UADC: J100.42 U200.61 | length 33.2
  Top Layer w0.2: v1@21.967,24.535 24.75,21.752 U200.61@24.75,20.425
  Bottom Layer w0.2: v1(21.967,24.513) 26.951,29.498 26.951,33.593 28.4,35.042 28.4,36.322 28.4,36.778 ; J100.42@25.5,48.6 25.5,42.272 28.4,39.371 28.4,36.778
BEMF_UN: J100.46 U200.14 | length 23.8
  Top Layer w0.2: U200.14@28.075,28.75 29.45,28.75 v1(29.85,29.15)
  Bottom Layer w0.2: J100.46@26.5,48.6 26.5,42.56 29.85,39.21 29.85,32.844 28.638,31.632 28.638,30.362 v1(29.85,29.15)
BEMF_UP: J100.45 U200.13 | length 25.7
  Top Layer w0.2: J100.45@26.25,48.85 26.25,43.123 29.604,39.769 29.604,35.421 30.675,34.35 v1(31.2,34.35) ; U200.13@28.075,28.25 30.05,28.25 v1(29.85,28.25)
  Bottom Layer w0.2: v1(29.85,28.25) 31.2,29.6 v1(31.2,34.35)
BEMF_VADC: J100.43 U200.62 | length 33.2
  Top Layer w0.2: v1(22.936,24.513) 25.25,22.198 U200.62@25.25,20.425 ; J100.43@25.75,48.85 25.75,42.977 28.95,39.777 v1(28.95,36.55)
  Bottom Layer w0.2: v1(22.936,24.513) 22.936,24.987 27.301,29.353 27.301,33.319 28.95,34.967 v1(28.95,36.55)
BEMF_VN: J100.48 U200.16 | length 21.1
  Top Layer w0.2: U200.16@28.075,29.75 28.075,30.275 v1(29.3,31.5)
  Bottom Layer w0.2: J100.48@27,48.6 27,43.013 30.239,39.774 30.239,32.439 v1(29.3,31.5)
BEMF_VP: J100.47 U200.15 | length 23.6
  Top Layer w0.2: J100.47@26.75,48.85 26.75,43.178 30.028,39.9 30.028,35.94 30.618,35.35 v1(31.2,35.35) ; U200.15@28.075,29.25 29.045,29.25 29.375,29.58 29.375,30.575 v1(30.3,31.5)
  Bottom Layer w0.2: v1(30.3,31.5) 30.589,31.789 30.589,34.739 v1(31.2,35.35)
BEMF_WADC: J100.44 U200.9 | length 26.5
  Top Layer w0.2: v1(26.5,27.05) 26.5,26.484 26.734,26.25 U200.9@28.075,26.25
  Bottom Layer w0.2: J100.44@26,48.6 26,42.397 29.5,38.897 29.5,34.758 27.651,32.909 27.651,28.201 v1(26.5,27.05)
BEMF_WN: C103.1 J100.50 U100.4 | length 20
  Top Layer w0.2: v1(31.2,36.55) 33.638,36.55 34.124,36.065 U100.4@35.45,36.065 35.475,36.09 C103.1@35.475,38.01
  Bottom Layer w0.2: J100.50@27.5,48.6 27.5,43.098 30.8,39.798 30.8,36.95 v1(31.2,36.55)
BEMF_WP: C100.1 C101.1 J100.49 R100.1 U100.3 | length 29.8
  Top Layer w0.2: J100.49@27.25,48.85 27.25,43.314 30.517,40.047 30.517,36.274 30.865,35.926 33.334,35.926 34.132,35.128 36.152,35.128 37.089,36.065 U100.3@38.05,36.065 ; C101.1@40.275,37.86 38.983,37.86 38.05,36.927 U100.3@38.05,36.065 ; R100.1@41.925,35.91 41.875,35.86 C100.1@40.225,35.86 40.02,36.065 U100.3@38.05,36.065
DRIVER_OCP: J100.25 U200.64 | length 35.1
  Top Layer w0.18: v1(18.157,36.059) 18.157,42.294 21.25,45.386 J100.25@21.25,48.85
  Top Layer w0.2: v1(19.35,26.05) 19.375,26.025 22.937,26.025 26.25,22.712 U200.64@26.25,20.425
  Bottom Layer w0.2: v1(18.157,36.059) 18.157,27.243 v1(19.35,26.05)
EDBG_ADC0: R201.1 R202.2 U300.K10 | length 19.7
  Top Layer w0.15: U300.K10@11.878,9.298 v2(12.336,9.298) ; v1(28.063,6.136) R202.2@28.954,6.136 28.913,6.095 R201.1@28.913,4.835
  Bottom Layer w0.15: v2(12.336,9.298) 24.034,9.298 27.196,6.136 v1(28.063,6.136)
EDBG_CDC_USART_RX: J200.2 U300.F9 | length 12
  Top Layer w0.15: U300.F9@11.226,11.899 11.572,11.553 12.306,11.553 14.227,9.633 20.922,9.633 21.35,10.061 J200.2@21.35,10.825
EDBG_CDC_USART_TX: R306.2 U300.E9 | length 6.8
  Top Layer w0.15: U300.E9@11.225,12.55 v2(11.55,12.875) 17.02,12.875 R306.2@17.619,13.474
EDBG_FORCE_BOOT: TP301.1 U300.H9 | length 29.2
  Top Layer w0.15: U300.H9@11.226,10.599 11.541,10.914 12.521,10.914 14.133,9.302 21.861,9.302 27.263,14.704 32.233,14.704 32.749,14.188 32.749,11.101 TP301.1@33.7,10.15
EDBG_ID1: J100.6 R300.1 U300.A1 | length 43.2
  Top Layer w0.15: R300.1@2.45,16.71 2.979,16.71 4.864,14.825 v2(5.7,14.825) U300.A1@6.025,15.15
  Bottom Layer w0.2: v2(5.7,14.825) 4.16,16.365 4.16,33.381 14.5,43.722 J100.6@14.5,48.6
EDBG_ID2: J100.4 R301.1 U300.B2 | length 44.9
  Top Layer w0.15: R301.1@2.452,15.222 3.272,15.222 4.32,14.174 v2(6.351,14.174) U300.B2@6.676,14.499
  Bottom Layer w0.2: v2(6.351,14.174) 5.629,14.174 3.81,15.993 3.81,33.568 14,43.758 J100.4@14,48.6
EDBG_JTAG_TCK: TP302.1 U300.K9 | length 24.5
  Top Layer w0.15: U300.K9@11.226,9.299 11.833,8.692 22.169,8.692 25.479,12.003 28.292,12.003 28.667,12.378 28.667,13.971 29.009,14.314 30.536,14.314 TP302.1@31.7,13.15
EDBG_JTAG_TDI: TP303.1 U300.K8 | length 21.6
  Top Layer w0.15: U300.K8@10.576,9.299 U300.K8@10.576,9.299 11.483,8.392 22.293,8.392 25.604,11.703 28.417,11.703 29.7,12.987 TP303.1@29.7,13.15
EDBG_JTAG_TDO: TP304.1 U300.J8 | length 23.3
  Top Layer w0.15: U300.J8@10.576,9.949 10.251,9.624 10.251,8.495 10.968,7.778 22.103,7.778 25.682,11.357 28.493,11.357 TP304.1@29.7,10.15
EDBG_JTAG_TMS: TP305.1 U300.H7 | length 20.2
  Top Layer w0.15: U300.H7@9.926,10.599 10.234,10.291 12.72,10.291 14.018,8.992 22.044,8.992 26.202,13.15 TP305.1@27.7,13.15
EDBG_RESET_N: TP306.1 U300.J9 | length 23.4
  Top Layer w0.15: v2@10.9,9.548 v2(10.9,9.625) 11.224,9.949 U300.J9@11.226,9.949 ; TP306.1@31.7,10.15 v1(31.7,11.422)
  Bottom Layer w0.15: v2(10.9,9.625) 11.584,9.625 11.874,9.916 22.737,9.916 24.243,11.422 v1(31.7,11.422)
EDBG_SPI_DGI_MISO: R307.1 U300.K2 | length 4.5
  Top Layer w0.15: U300.K2@6.675,9.3 v2(6.35,8.975) 6.35,7.946 7.6,6.696 R307.1@7.6,5.5
EDBG_SPI_DGI_MOSI: U200.27 U300.K3 | length 36.8
  Top Layer w0.15: v2(7.001,8.974) U300.K3@7.326,9.299 ; U200.27@21.25,31.575 v1@21.25,33
  Bottom Layer w0.15: v2(7.001,8.974) 5.959,10.017 5.959,13.037 7.019,14.096 7.019,15.315 7.837,16.134 14.813,16.134 17.725,19.045 17.725,21.183 20.225,23.683 20.225,31.975 v1@21.25,33
  other v1: 21.25,33.075
EDBG_SPI_DGI_SCK: U200.28 U300.J4 | length 33.4
  Top Layer w0.15: v2(7.65,9.625) U300.J4@7.975,9.95 ; v1@20.75,30.15 U200.28@20.75,31.575
  Bottom Layer w0.15: v2(7.65,9.625) 6.893,9.625 6.607,9.91 6.607,11.153 7.515,12.06 7.515,14.175 7.257,14.432 7.257,15.129 7.962,15.834 14.938,15.834 18.025,18.921 18.025,21.059 20.75,23.784 v1@20.75,30.15
  other v1: 20.75,30.075
EDBG_SPI_DGI_SS: J201.1 U200.26 U300.G5 | length 42
  Top Layer w0.15: U300.G5@8.625,11.25 v2(8.95,10.925) ; J201.1@18.7,10.825 18.7,10.357 18.85,10.207 19.685,10.207 20.109,10.631 v1(20.109,13.45) ; v1@21.75,30.163 U200.26@21.75,31.575
  Bottom Layer w0.15: v2(8.95,10.925) 7.909,11.966 7.909,13.513 8.796,14.4 12.595,14.4 14.022,12.973 14.494,12.973 14.503,12.982 16.3,12.982 16.309,12.973 19.632,12.973 v1(20.109,13.45) 20.109,15.142 18.325,16.926 18.325,20.934 21.05,23.659 21.05,29.375 v1(21.75,30.075) ; v1@21.712,30.112 v1@21.75,30.15
EDBG_USB_FS_N: R308.2 U300.B9 | length 4.4
  Top Layer w0.125: U300.B9@11.226,14.499 11.529,14.802 11.529,15.533 13.2,17.205 R308.2@13.2,18.05
EDBG_USB_FS_P: R309.2 U300.B8 | length 4.2
  Top Layer w0.125: U300.B8@10.576,14.499 10.924,14.847 10.924,16.043 12.15,17.27 R309.2@12.15,18.05
EDBG_USB_HS_N: J100.3 R308.1 U300.A9 | length 39.3
  Top Layer w0.125: U300.A9@11.226,15.149 11.226,15.791 12.675,17.239 12.675,18.525 R308.1@13.2,19.05
  Top Layer w0.18: R308.1@13.2,19.05 12.896,19.354 12.896,22.278 7.685,27.489 7.685,37.161 13.74,43.215 13.74,48.363 13.75,48.373 J100.3@13.75,48.85
EDBG_USB_HS_P: J100.1 R309.1 U300.A8 | length 39.1
  Top Layer w0.125: U300.A8@10.576,15.149 10.576,16.162 11.608,17.193 11.608,18.508 R309.1@12.15,19.05
  Top Layer w0.18: R309.1@12.15,19.05 12.435,19.335 12.435,22.06 7.205,27.29 7.205,37.359 13.26,43.414 13.26,48.294 13.25,48.304 J100.1@13.25,48.85
ENCODER_A: J100.55 U101.3 U200.12 | length 32.4
  Top Layer w0.2: U200.12@28.075,27.75 29.224,27.75 29.674,27.3 30.629,27.3 ; J100.55@28.75,48.85 28.75,44.275 v1(31.652,41.373) ; U101.3@30.975,29.4 30.975,28.891 30.665,28.581 30.665,27.336 30.629,27.3 ; v1(33.65,28.3) 32.65,27.3 30.629,27.3
  Bottom Layer w0.2: v1(31.652,41.373) 34.95,38.075 34.95,29.059 34.191,28.3 v1(33.65,28.3)
ENCODER_B: J100.56 U101.1 U200.23 | length 36.4
  Top Layer w0.2: U200.23@23.25,31.575 23.25,30.494 23.52,30.224 26.436,30.224 29.962,33.75 v1(34.2,33.75) 34.2,32.799 33.805,32.404 ; U101.1@30.975,30.4 31.05,30.475 31.05,31.493 31.96,32.404 33.805,32.404 ; 33.801,32.399 33.805,32.404
  Bottom Layer w0.2: J100.56@29,48.6 29,43.172 34.2,37.972 v1(34.2,33.75)
ENCODER_EN: J100.58 U200.49 | length 46
  Top Layer w0.2: U200.49@18.75,20.425 18.75,19.325 v1(19.15,18.925)
  Bottom Layer w0.2: v1(19.15,18.925) 21.398,21.173 28.167,21.173 35.873,28.88 35.873,38.896 32.747,42.022 30.839,42.022 29.5,43.362 29.5,46.444 J100.58@29.5,48.6
ENCODER_Z: J100.57 U200.50 | length 43.1
  Top Layer w0.2: U200.50@19.25,20.425 19.25,21.423 19.727,21.9 v1@20.5,21.9 ; J100.57@29.25,48.85 29.25,44.725 v1(32.968,41.007)
  Bottom Layer w0.2: v1@20.5,21.9 20.89,21.51 21.24,21.51 21.253,21.523 28.022,21.523 35.484,28.985 35.484,38.491 v1(32.968,41.007)
  other v1: 20.5,21.925
EXT1_RXD: J100.26 U200.30 | length 18.5
  Top Layer w0.2: U200.30@19.75,31.575 19.75,34.316 19.95,34.516 v1(19.95,35.1)
  Bottom Layer w0.2: v1(19.95,35.1) 19,36.05 19,42.497 21.5,44.997 J100.26@21.5,48.6
EXT1_TXD: J100.27 U200.29 | length 18.7
  Top Layer w0.2: U200.29@20.25,31.575 20.25,33 v1(21.25,34) ; v1(20.296,42.834) 20.296,43.875 21.75,45.328 J100.27@21.75,48.85
  Bottom Layer w0.2: v1(20.296,42.834) 20.83,42.301 20.83,34.42 v1(21.25,34)
FLASH_MISO: J100.15 U200.41 | length 30.2
  Top Layer w0.2: U200.41@16.925,25.75 14.144,25.75 11.183,28.71 11.183,33.769 14.85,37.436 14.85,39.619 16.559,41.328 16.559,42.661 18.75,44.852 J100.15@18.75,48.85
FLASH_MOSI: J100.17 U200.39 | length 28.7
  Top Layer w0.2: U200.39@16.925,26.75 14.285,26.75 11.942,29.093 11.942,33.339 15.95,37.347 15.95,40.224 16.909,41.183 16.909,42.516 19.25,44.857 J100.17@19.25,48.85
FLASH_SCK: J100.16 U200.40 | length 29.2
  Top Layer w0.2: v1(15.4,38.6) 15.4,37.406 11.588,33.594 11.588,28.836 14.174,26.25 U200.40@16.925,26.25
  Bottom Layer w0.2: v1(15.4,38.6) 15.4,41.565 19,45.165 J100.16@19,48.6
FLASH_SS: J100.14 U200.42 | length 30.7
  Top Layer w0.2: v1(14.25,38.6) 14.25,37.393 10.833,33.976 10.833,28.565 14.149,25.25 U200.42@16.925,25.25
  Bottom Layer w0.2: v1(14.25,38.6) 14.25,40.91 18.5,45.16 J100.14@18.5,48.6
